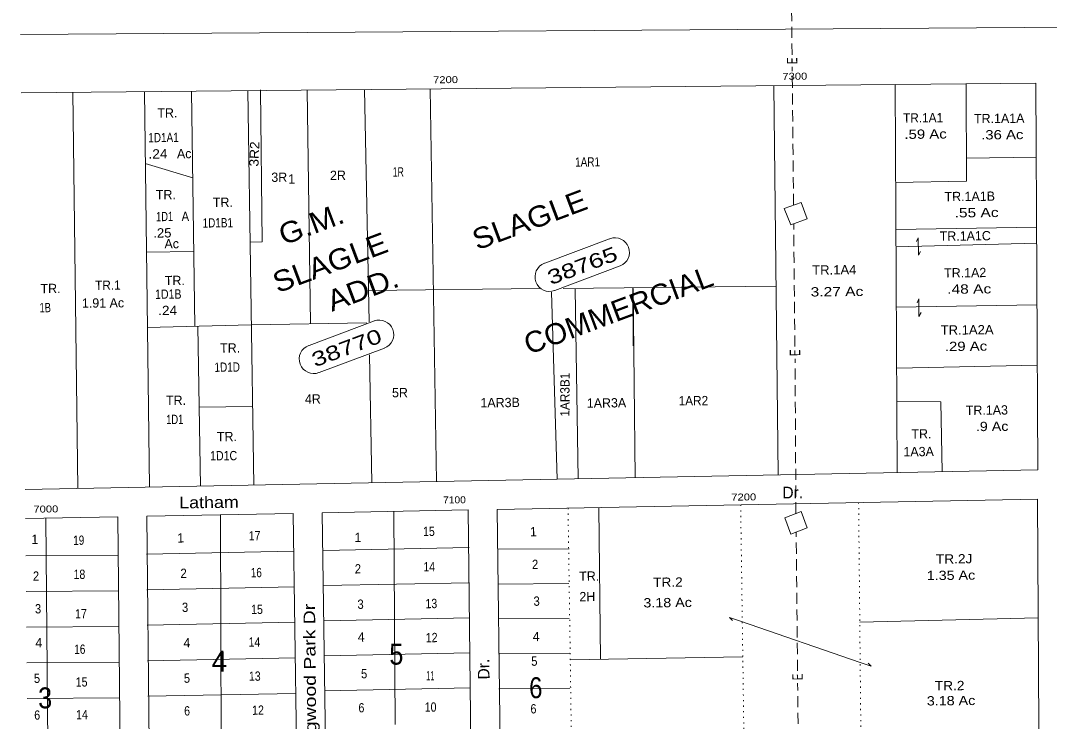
# Model space of a CAD drawing. Extents: x 2356373 to 2371954, y 6966197 to 6989612.
# Drawn here: x 2359922 to 2361692, y 6979345 to 6980551 of the extents above; entities that cross this region are included whole.
import ezdxf

# ---------------------------------------------------------------- set-up
doc = ezdxf.new("R2010")
doc.units = 0
doc.header["$LTSCALE"] = 6.4
doc.linetypes.add('DOTTED', pattern=[1.5, 0.3, -1.2])
doc.linetypes.add('MEDIUM_DASHED', pattern=[4.5, 3, -1.5])
for name, color, linetype in [('10', 7, 'Continuous'), ('11', 7, 'Continuous'), ('18', 7, 'Continuous'), ('22', 7, 'Continuous'), ('24', 7, 'Continuous')]:
    doc.layers.add(name, color=color, linetype=linetype)
for name, color, linetype, lineweight in [('12', 7, 'Continuous', 13), ('13', 7, 'Continuous', 13), ('15', 7, 'Continuous', 13), ('16', 7, 'DOTTED', 13), ('17', 7, 'Continuous', 13), ('19', 7, 'Continuous', 13), ('4', 7, 'Continuous', 13), ('5', 7, 'DOTTED', 13), ('6', 7, 'DOTTED', 13), ('7', 7, 'Continuous', 13)]:
    doc.layers.add(name, color=color, linetype=linetype, lineweight=lineweight)

msp = doc.modelspace()

# ---------------------------------------------------------------- linework, layer by layer
at = {"layer": '13'}
msp.add_line((2361160.405, 6979517.612), (2361366.045, 6979446.852), dxfattribs=at)
for points in [[(2361462.906, 6980170.81), (2361465.841, 6980177.337), (2361466.136, 6980147.349), (2361470.071, 6980153.885)], [(2361463.939, 6980065.649), (2361466.873, 6980072.176), (2361467.168, 6980042.186), (2361471.104, 6980048.723)], [(2361160.405, 6979517.612), (2361141.345, 6979524.223), (2361146.395, 6979518.874)], [(2361366.045, 6979446.852), (2361385.105, 6979440.241), (2361380.054, 6979445.589)]]:
    msp.add_lwpolyline(points, dxfattribs=at)
at = {"layer": '15'}
for p, q in [((2359929.506, 6979744.358), (2361671.71, 6979778.066)), ((2361671.2, 6979728.074), (2360741.626, 6979710.047)), ((2360691.648, 6979709.155), (2360440.762, 6979704.292)), ((2360440.762, 6979704.292), (2360447.742, 6979197.195)), ((2360697.158, 6979249.833), (2360691.648, 6979709.155)), ((2360741.626, 6979710.047), (2360755.59, 6978593.681)), ((2359929.997, 6979694.377), (2360088.924, 6979697.437)), ((2360390.786, 6979703.302), (2360138.901, 6979698.428)), ((2360138.901, 6979698.428), (2360144.451, 6979133.434)), ((2360397.86, 6979186.709), (2360390.786, 6979703.302))]:
    msp.add_line(p, q, dxfattribs=at)
for points in [[(2361671.71, 6979778.066), (2361668.174, 6980443.355), (2359922.799, 6980427.11)], [(2361595.961, 6979042.019), (2361674.934, 6979042.594), (2361671.2, 6979728.074)], [(2360088.924, 6979697.437), (2360094.568, 6979122.846), (2359935.938, 6979089.495)]]:
    msp.add_lwpolyline(points, dxfattribs=at)
at = {"layer": '16', "linetype": 'Continuous'}
for p, q in [((2360312.66, 6980430.74), (2360323.326, 6979752.025)), ((2360637.181, 6979758.109), (2360626.547, 6980433.723)), ((2361217.335, 6980439.127), (2361224.915, 6979769.378))]:
    msp.add_line(p, q, dxfattribs=at)
at = {"layer": '16'}
msp.add_lwpolyline([(2360863.569, 6979712.445), (2360876.032, 6978850.797), (2361171.891, 6978857.101), (2361175.407, 6978600.904)], dxfattribs=at)
at = {"layer": '17'}
for p, q in [((2360823.442, 6980133.638), (2360934.997, 6980175.822)), ((2360840.898, 6980086.822), (2360953.453, 6980129.016)), ((2360417.939, 6979992.292), (2360530.495, 6980034.385)), ((2360435.395, 6979945.475), (2360547.952, 6979987.57))]:
    msp.add_line(p, q, dxfattribs=at)
for centre, start, end in [((2360944.225, 6980152.419), 290.56276, 110.56276), ((2360831.67, 6980110.224), 110.56276, 290.56276), ((2360538.723, 6980010.973), 290.56276, 110.56276), ((2360426.167, 6979968.878), 110.56276, 290.56276)]:
    msp.add_arc(centre, 24.992, start, end, dxfattribs=at)
at = {"layer": '4'}
msp.add_line((2365919.817, 6980567.793), (2359921.814, 6980527.373), dxfattribs=at)
at = {"layer": '5', "linetype": 'Continuous'}
for p, q in [((2360215.694, 6980429.887), (2360221.67, 6980025.054)), ((2361426.261, 6980441.079), (2361429.82, 6979773.391)), ((2360011.766, 6980427.984), (2360020.464, 6979746.151)), ((2360134.723, 6980429.091), (2360143.407, 6979748.559)), ((2360135.937, 6980305.537), (2360218.162, 6980280.351)), ((2361548.474, 6980314.312), (2361669.425, 6980316.1)), ((2361427.711, 6980191.759), (2361669.604, 6980195.935)), ((2361669.877, 6980168.044), (2361428, 6980162.168)), ((2360138.437, 6980152.602), (2360219.403, 6980153.998)), ((2361428.023, 6980058.098), (2361669.917, 6980062.173)), ((2360139.712, 6980022.949), (2360318.619, 6980027.505)), ((2360226.668, 6980025.104), (2360231.366, 6979750.222)), ((2361429.053, 6979953.136), (2361670.94, 6979958.111)), ((2360229.035, 6979885.863), (2360320.994, 6979887.466)), ((2360919.113, 6979452.059), (2360916.545, 6979713.463)), ((2361672.209, 6979523.639), (2361365.362, 6979516.426)), ((2361164.004, 6979456.565), (2360867.136, 6979451.148))]:
    msp.add_line(p, q, dxfattribs=at)
for points in [[(2361548.216, 6980442.276), (2361548.86, 6980275.027), (2361426.916, 6980272.63)], [(2361428.618, 6979895.647), (2361504.602, 6979895.294), (2361506.785, 6979774.847)]]:
    msp.add_lwpolyline(points, dxfattribs=at)
at = {"layer": '5'}
for points in [[(2361363.341, 6979722.151), (2361368.001, 6979247.624), (2361673.853, 6979254.527)], [(2361160.435, 6979718.159), (2361167.07, 6979246.151), (2361065.113, 6979244.449), (2361069.08, 6979044.241), (2361169.028, 6979046.723), (2361171.891, 6978857.101)]]:
    msp.add_lwpolyline(points, dxfattribs=at)
at = {"layer": '6', "linetype": 'Continuous'}
for p, q in [((2360420.573, 6980029.507), (2360414.622, 6980431.741)), ((2360521.516, 6980032.598), (2360513.588, 6980432.613)), ((2360854.859, 6980090.356), (2361221.726, 6980093.961)), ((2360519.981, 6980087.068), (2360814.873, 6980089.964)), ((2360834.925, 6980084.163), (2360845.086, 6979762.05)), ((2360881.07, 6979762.803), (2360875.867, 6980088.965)), ((2360974.816, 6980091.437), (2360975.796, 6979991.572)), ((2360975.827, 6980090.446), (2360979.025, 6979764.665)), ((2360517.529, 6980031.359), (2360318.619, 6980027.505)), ((2360526.233, 6979755.918), (2360522.068, 6979976.219)), ((2360566.308, 6979339.924), (2360563.706, 6979706.699)), ((2359969.82, 6979202.298), (2359964.979, 6979695.12)), ((2360267.088, 6979268.902), (2360265.843, 6979700.875)), ((2360391.425, 6979638.125), (2360138.543, 6979633.042)), ((2360693.283, 6979644.489), (2360442.4, 6979639.425)), ((2360865.256, 6979642.579), (2360743.296, 6979641.681)), ((2360089.573, 6979631.261), (2359930.628, 6979630.101)), ((2360693.876, 6979584.112), (2360442.993, 6979579.046)), ((2360742.887, 6979581.693), (2360864.845, 6979582.591)), ((2360090.176, 6979569.984), (2359931.229, 6979568.823)), ((2360393.025, 6979577.057), (2360139.142, 6979571.964)), ((2360393.625, 6979515.979), (2360139.744, 6979510.786)), ((2360694.469, 6979523.733), (2360443.586, 6979518.669)), ((2360865.435, 6979522.613), (2360743.476, 6979521.715)), ((2360090.779, 6979508.706), (2359931.832, 6979507.545)), ((2360695.061, 6979463.355), (2360444.179, 6979458.291)), ((2360744.065, 6979461.737), (2360866.023, 6979462.634)), ((2360091.38, 6979447.428), (2359932.433, 6979446.267)), ((2360394.226, 6979454.802), (2360140.343, 6979449.709)), ((2360695.654, 6979402.977), (2360444.771, 6979397.914)), ((2360091.982, 6979386.151), (2359933.034, 6979384.989)), ((2360394.827, 6979393.723), (2360140.943, 6979388.631)), ((2360866.613, 6979402.656), (2360744.654, 6979401.758))]:
    msp.add_line(p, q, dxfattribs=at)
msp.add_lwpolyline([(2360317.218, 6980170.153), (2360337.211, 6980170.352), (2360334.642, 6980431.855)], dxfattribs=at)
at = {"layer": '7', "linetype": 'MEDIUM_DASHED'}
for p, q in [((2361248.803, 6980492.521), (2361247.428, 6980632.469)), ((2361251.344, 6980233.715), (2361249.01, 6980471.428)), ((2361253.735, 6979990.304), (2361251.658, 6980201.727)), ((2361255.556, 6979703.198), (2361253.943, 6979969.211)), ((2361258.216, 6979432.396), (2361255.869, 6979671.309)), ((2361260.527, 6979197.122), (2361258.422, 6979411.305))]:
    msp.add_line(p, q, dxfattribs=at)
at = {"layer": '7'}
for points in [[(2361246.679, 6980199.878), (2361274.569, 6980210.35), (2361264.294, 6980238.441), (2361235.406, 6980227.96)], [(2361246.907, 6979667.723), (2361274.796, 6979678.293), (2361264.522, 6979706.385), (2361236.633, 6979695.813)]]:
    msp.add_lwpolyline(points, close=True, dxfattribs=at)

# ---------------------------------------------------------------- texts
at = {"layer": '10'}
for s, p in [('TR.', (2360157.159, 6980384.125)), ('TR.1A1A', (2361561.879, 6980374.528)), ('TR.', (2360154.541, 6980243.536)), ('TR.1A1B', (2361511.21, 6980240.366)), ('TR.', (2360252.644, 6980230.404)), ('TR.1A1C', (2361502.881, 6980172.303)), ('TR.', (2360169.987, 6980095.928)), ('TR.1A2', (2361510.5, 6980109.095)), ('TR.', (2359956.18, 6980082.13)), ('TR.', (2360172.013, 6979889.702)), ('TR.1A3', (2361547.812, 6979872.724)), ('TR.', (2361454.237, 6979832.015)), ('TR.', (2360259.602, 6979827.279)), ('1A3A', (2361440.542, 6979801.389)), ('TR.', (2360882.793, 6979587.267)), ('2H', (2360883.14, 6979552.079))]:
    msp.add_text(s, height=15.99, rotation=0.563, dxfattribs=at).set_placement(p)
for s, width, p in [('TR.1A1', 0.95, (2361439.901, 6980375.629)), ('1D1A1', 0.8, (2360141.579, 6980341.782)), ('1D1', 0.75, (2360154.91, 6980205.95)), ('A', 0.9, (2360198.895, 6980206.382)), ('1D1B1', 0.8, (2360234.996, 6980195.04)), ('TR.1A4', 1.05, (2361283.512, 6980113.964)), ('TR.1', 0.95, (2360050.099, 6980087.751)), ('1D1B', 0.85, (2360153.223, 6980072.37)), ('1B', 0.75, (2359954.502, 6980049.323)), ('TR.1A2A', 1.05, (2361504.468, 6980010.661)), ('1D1D', 0.8, (2360255.43, 6979946.807)), ('1D1', 0.75, (2360172.334, 6979856.914)), ('1D1C', 0.85, (2360247.928, 6979794.374)), ('TR.2J', 1.1, (2361496.341, 6979616.787)), ('TR.2', 1.1, (2361009.862, 6979576.818)), ('TR.2', 1.1, (2361494.484, 6979398.726))]:
    msp.add_text(s, height=15.99, rotation=0.563, dxfattribs=dict(at, width=width)).set_placement(p)
at = {"layer": '11'}
for s, width, p in [('.59 Ac', 1.2, (2361442.175, 6980347.559)), ('.36 Ac', 1.2, (2361574.15, 6980346.556)), ('.24', 1.1, (2360141.854, 6980313.693)), ('.55 Ac', 1.25, (2361528.479, 6980212.443)), ('.25', 1.05, (2360150.188, 6980177.81)), ('3.27 Ac', 1.25, (2361280.881, 6980076.448)), ('.48 Ac', 1.25, (2361515.774, 6980081.054)), ('.24', 1.1, (2360158.498, 6980044.328)), ('.29 Ac', 1.2, (2361511.743, 6979982.54)), ('.9 Ac', 1.15, (2361565.082, 6979844.801)), ('1.35 Ac', 1.15, (2361480.624, 6979588.44)), ('3.18 Ac', 1.15, (2360993.214, 6979541.464)), ('3.18 Ac', 1.15, (2361480.742, 6979372.799))]:
    msp.add_text(s, height=15.99, rotation=0.563, dxfattribs=dict(at, width=width)).set_placement(p)
for s, p in [('Ac', (2360190.837, 6980314.174)), ('Ac', (2360169.365, 6980159.204)), ('1.91 Ac', (2360027.407, 6980057.037)), ('TR.', (2360265.104, 6979979.693))]:
    msp.add_text(s, height=15.99, rotation=0.563, dxfattribs=at).set_placement(p)
at = {"layer": '12'}
for s, rotation, width, p in [('3R2', 87.699, 1.1, (2360330.94, 6980299.755)), ('1AR1', 0.563, 0.8, (2360875.795, 6980299.808)), ('1R', 0.563, 0.7, (2360562.049, 6980282.629)), ('1AR3B1', 89.976, 0.95, (2360866.023, 6979869.827)), ('1AR2', 0.563, 0.95, (2361053.785, 6979888.966)), ('17', 0.563, 0.85, (2360314.264, 6979656.662)), ('15', 0.563, 0.85, (2360614.11, 6979664.307)), ('19', 0.563, 0.8, (2360012.42, 6979649.1)), ('2', 0.563, 0.9, (2360496.774, 6979599.87)), ('14', 0.563, 0.85, (2360614.707, 6979603.428)), ('2', 0.563, 0.9, (2360801.616, 6979607.562)), ('2', 0.563, 0.9, (2359943.044, 6979587.433)), ('18', 0.563, 0.85, (2360012.996, 6979590.421)), ('2', 0.563, 0.9, (2360196.929, 6979592.227)), ('16', 0.563, 0.8, (2360317.885, 6979593.415)), ('3', 0.563, 0.9, (2359946.596, 6979531.183)), ('3', 0.563, 0.9, (2360199.504, 6979533.667)), ('15', 0.563, 0.85, (2360318.506, 6979530.137)), ('3', 0.563, 0.9, (2360501.37, 6979539.032)), ('13', 0.563, 0.85, (2360618.327, 6979540.18)), ('3', 0.563, 0.9, (2360804.237, 6979544.306)), ('17', 0.563, 0.85, (2360015.663, 6979522.464)), ('12', 0.563, 0.85, (2360618.903, 6979481.602)), ('16', 0.563, 0.8, (2360014.261, 6979461.566)), ('14', 0.563, 0.85, (2360314.059, 6979473.909)), ('5', 0.563, 0.9, (2360800.253, 6979441.094)), ('5', 0.563, 0.9, (2359944.771, 6979411.597)), ('15', 0.563, 0.85, (2360016.814, 6979405.306)), ('5', 0.563, 0.9, (2360202.7, 6979411.832)), ('13', 0.563, 0.85, (2360314.636, 6979415.23)), ('5', 0.563, 0.9, (2360507.542, 6979419.524)), ('11', 0.563, 0.55, (2360619.548, 6979415.925)), ('6', 0.563, 0.85, (2360203.253, 6979355.552)), ('12', 0.563, 0.85, (2360320.209, 6979356.701)), ('6', 0.563, 0.85, (2360503.121, 6979360.896)), ('10', 0.563, 0.85, (2360617.078, 6979362.015)), ('6', 0.563, 0.85, (2360799.058, 6979359.104)), ('6', 0.563, 0.85, (2359945.392, 6979348.319)), ('14', 0.563, 0.85, (2360017.367, 6979349.028))]:
    msp.add_text(s, height=15.99, rotation=rotation, dxfattribs=dict(at, width=width)).set_placement(p)
for s, p in [('3R', (2360353.192, 6980273.58)), ('2R', (2360454.133, 6980276.87)), ('1', (2360382.214, 6980270.665)), ('5R', (2360560.779, 6979902.918)), ('4R', (2360410.927, 6979892.049)), ('1AR3B', (2360712.908, 6979885.617)), ('1AR3A', (2360895.864, 6979885.116)), ('1', (2360191.332, 6979653.154)), ('1', (2360496.245, 6979653.85)), ('1', (2360798.065, 6979663.814)), ('1', (2359940.423, 6979650.69)), ('4', (2360501.923, 6979482.752)), ('4', (2360802.836, 6979483.408)), ('4', (2359947.171, 6979472.604)), ('4', (2360202.1, 6979472.809))]:
    msp.add_text(s, height=15.99, rotation=0.563, dxfattribs=at).set_placement(p)
at = {"layer": '17', "width": 1.35}
for s, p in [('38765', (2360833.811, 6980095.848)), ('38770', (2360428.307, 6979954.502))]:
    msp.add_text(s, height=24.99, rotation=20.563, dxfattribs=at).set_placement(p)
at = {"layer": '18'}
for s, width, p in [('SLAGLE', 1.1, (2360707.258, 6980155.59)), ('G.M.', 1.1, (2360374.263, 6980164.116)), ('SLAGLE', 1.1, (2360364.073, 6980081.938)), ('ADD.', 1.1, (2360457.36, 6980050.064)), ('COMMERCIAL', 1.05, (2360795.998, 6979976.01))]:
    msp.add_text(s, height=35.99, rotation=20.563, dxfattribs=dict(at, width=width)).set_placement(p)
at = {"layer": '19'}
for rotation, p in [(0.563, (2361232.308, 6979729.063)), (90.794, (2360728.502, 6979417.696))]:
    msp.add_text('Dr.', height=19.99, rotation=rotation, dxfattribs=at).set_placement(p)
for s, rotation, width, p in [('Latham', 0.563, 1.15, (2360194.752, 6979711.974)), ('Dogwood Park Dr', 90.563, 1.25, (2360430.892, 6979284.208))]:
    msp.add_text(s, height=19.99, rotation=rotation, dxfattribs=dict(at, width=width)).set_placement(p)
at = {"layer": '22'}
for s, width, p in [('5', 0.9, (2360556.298, 6979442.997)), ('6', 0.85, (2360796.802, 6979385.276)), ('3', 0.9, (2359952.199, 6979367.782))]:
    msp.add_text(s, height=35.99, rotation=0.563, dxfattribs=dict(at, width=width)).set_placement(p)
msp.add_text('4', height=35.99, rotation=0.563, dxfattribs=at).set_placement((2360250.501, 6979430.696))
at = {"layer": '24'}
for s, width, p in [('7200', 1.2, (2360631.451, 6980443.268)), ('7300', 1.2, (2361232.233, 6980449.17)), ('7100', 1.1, (2360648.55, 6979720.43)), ('7200', 1.2, (2361144.368, 6979725.299)), ('7000', 1.2, (2359943.891, 6979704.611))]:
    msp.add_text(s, height=12, rotation=0.563, dxfattribs=dict(at, width=width)).set_placement(p)
at = {"layer": '7', "width": 0.7}
for p in [(2361257.957, 6980476.515), (2361262.892, 6979974.197), (2361267.371, 6979416.391)]:
    msp.add_text('E', height=17.99, rotation=90.529, dxfattribs=at).set_placement(p)

doc.saveas('drawing.dxf')
